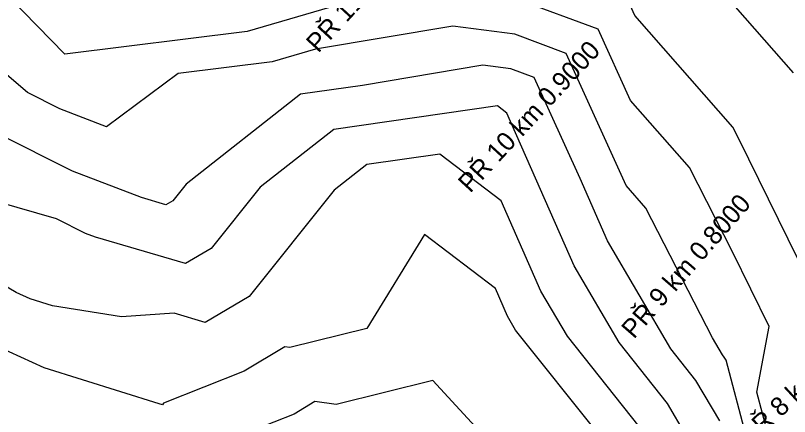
# Model space of a CAD drawing. Extents: x -549394 to -546608, y -1037055 to -1033629.
# Drawn here: x -548577.2 to -548202.8, y -1034491.4 to -1034297.2 of the extents above; entities that cross this region are included whole.
import ezdxf

# ---------------------------------------------------------------- set-up
doc = ezdxf.new("R2010")
doc.units = 0
for name, color, linetype in [('hlavni_vrst', 7, 'Continuous'), ('norm_vrst', 7, 'Continuous'), ('x_popis_pricne_rezy_C21', 7, 'Continuous')]:
    doc.layers.add(name, color=color, linetype=linetype)

msp = doc.modelspace()

# ---------------------------------------------------------------- linework, layer by layer
at = {"layer": 'hlavni_vrst'}
for p, q in [((-548351.11, -1034321.27), (-548409.39, -1034331.03)), ((-548337.6, -1034323), (-548351.11, -1034321.27)), ((-548326.39, -1034327.19), (-548337.6, -1034323)), ((-548304.14, -1034376.15), (-548326.39, -1034327.19)), ((-548409.39, -1034331.03), (-548439.33, -1034335.33)), ((-548439.33, -1034335.33), (-548494.69, -1034378.78)), ((-548549.58, -1034372.48), (-548588.64, -1034352.94)), ((-548516.22, -1034385.34), (-548549.58, -1034372.48)), ((-548494.69, -1034378.78), (-548501.11, -1034386.84)), ((-548290.88, -1034406.26), (-548304.14, -1034376.15)), ((-548504.43, -1034388.79), (-548516.22, -1034385.34)), ((-548501.11, -1034386.84), (-548504.43, -1034388.79)), ((-548260.31, -1034458.52), (-548290.88, -1034406.26)), ((-548248.12, -1034473.83), (-548260.31, -1034458.52)), ((-548236.61, -1034493.43), (-548248.12, -1034473.83))]:
    msp.add_line(p, q, dxfattribs=at)
at = {"layer": 'norm_vrst'}
for p, q in [((-548553.29, -1034315.9), (-548606.49, -1034261.26)), ((-548407.21, -1034287.96), (-548465.15, -1034304.87)), ((-548295.38, -1034303.83), (-548333.91, -1034289.41)), ((-548277.6, -1034297.17), (-548279.88, -1034292.16)), ((-548229.05, -1034292.94), (-548201.05, -1034324.93)), ((-548230.26, -1034351.27), (-548277.6, -1034297.17)), ((-548365.73, -1034302.37), (-548432.07, -1034313.48)), ((-548335.75, -1034306.21), (-548365.73, -1034302.37)), ((-548279.69, -1034338.37), (-548295.38, -1034303.83)), ((-548465.15, -1034304.87), (-548553.29, -1034315.9)), ((-548310.89, -1034315.51), (-548335.75, -1034306.21)), ((-548432.07, -1034313.48), (-548453.11, -1034319.62)), ((-548281.78, -1034379.57), (-548310.89, -1034315.51)), ((-548571.43, -1034334.47), (-548587.9, -1034320.42)), ((-548453.11, -1034319.62), (-548498.48, -1034325.29)), ((-548498.48, -1034325.29), (-548533.12, -1034351.03)), ((-548555.75, -1034342.31), (-548571.43, -1034334.47)), ((-548344.13, -1034340.96), (-548423.27, -1034352.32)), ((-548339.6, -1034344.42), (-548344.13, -1034340.96)), ((-548251.29, -1034370.83), (-548279.69, -1034338.37)), ((-548533.12, -1034351.03), (-548555.75, -1034342.31)), ((-548306.99, -1034418.43), (-548339.6, -1034344.42)), ((-548423.27, -1034352.32), (-548458.85, -1034380.25)), ((-548227.23, -1034357.2), (-548230.26, -1034351.27)), ((-548190.3, -1034432.56), (-548227.23, -1034357.2)), ((-548372.03, -1034364.26), (-548407.2, -1034369.31)), ((-548342.35, -1034386.93), (-548372.03, -1034364.26)), ((-548407.2, -1034369.31), (-548423.02, -1034381.72)), ((-548230.4, -1034411.67), (-548251.29, -1034370.83)), ((-548458.85, -1034380.25), (-548482.64, -1034410.07)), ((-548423.02, -1034381.72), (-548464.16, -1034433.3)), ((-548272.31, -1034390.39), (-548281.78, -1034379.57)), ((-548557.36, -1034395.67), (-548588.13, -1034386.75)), ((-548323.1, -1034430.61), (-548342.35, -1034386.93)), ((-548240.14, -1034453.28), (-548272.31, -1034390.39)), ((-548543.41, -1034402.65), (-548557.36, -1034395.67)), ((-548576.92, -1034431.22), (-548628.29, -1034401.66)), ((-548538.56, -1034404.52), (-548543.41, -1034402.65)), ((-548494.91, -1034417.3), (-548538.56, -1034404.52)), ((-548379.33, -1034403.29), (-548407.26, -1034448.7)), ((-548345.09, -1034429.44), (-548379.33, -1034403.29)), ((-548482.64, -1034410.07), (-548494.91, -1034417.3)), ((-548212.7, -1034447.78), (-548230.4, -1034411.67)), ((-548285.31, -1034455.5), (-548306.99, -1034418.43)), ((-548570.13, -1034434.34), (-548576.92, -1034431.22)), ((-548339.21, -1034442.78), (-548345.09, -1034429.44)), ((-548310.3, -1034452.49), (-548323.1, -1034430.61)), ((-548559.27, -1034437.72), (-548570.13, -1034434.34)), ((-548464.16, -1034433.3), (-548485.39, -1034445.81)), ((-548525.99, -1034443.12), (-548559.27, -1034437.72)), ((-548500.52, -1034441.38), (-548525.99, -1034443.12)), ((-548485.39, -1034445.81), (-548500.52, -1034441.38)), ((-548335.3, -1034449.47), (-548339.21, -1034442.78)), ((-548407.26, -1034448.7), (-548444.44, -1034457.91)), ((-548289.24, -1034507.32), (-548335.3, -1034449.47)), ((-548218.68, -1034479.5), (-548212.7, -1034447.78)), ((-548563.3, -1034467.8), (-548599.62, -1034451.14)), ((-548275.53, -1034496.16), (-548310.3, -1034452.49)), ((-548235.31, -1034461.54), (-548240.14, -1034453.28)), ((-548446.94, -1034457.6), (-548466.59, -1034469.42)), ((-548444.44, -1034457.91), (-548446.94, -1034457.6)), ((-548261.82, -1034485), (-548285.31, -1034455.5)), ((-548234.41, -1034462.67), (-548235.31, -1034461.54)), ((-548233.55, -1034464.12), (-548234.41, -1034462.67)), ((-548211.81, -1034546.33), (-548233.55, -1034464.12)), ((-548507.64, -1034485.13), (-548563.3, -1034467.8)), ((-548466.59, -1034469.42), (-548505.56, -1034484.82)), ((-548375.32, -1034473.87), (-548422.06, -1034485.46)), ((-548343.1, -1034509.02), (-548375.32, -1034473.87)), ((-548202.9, -1034539.18), (-548218.68, -1034479.5)), ((-548506.07, -1034485.64), (-548507.64, -1034485.13)), ((-548505.56, -1034484.82), (-548506.07, -1034485.64)), ((-548432.37, -1034484.14), (-548442.35, -1034490.14)), ((-548422.06, -1034485.46), (-548432.37, -1034484.14)), ((-548239.67, -1034522.74), (-548261.82, -1034485)), ((-548442.35, -1034490.14), (-548462.11, -1034497.96))]:
    msp.add_line(p, q, dxfattribs=at)

# ---------------------------------------------------------------- texts
at = {"layer": 'x_popis_pricne_rezy_C21'}
for s, rotation, p in [('PŘ 11 km 1.0000', 47.3078, (-548430.79, -1034315.67)), ('PŘ 10 km 0.9000', 47.3078, (-548357.29, -1034383.48)), ('PŘ 9 km 0.8000', 48.9228, (-548278.09, -1034454.16)), ('PŘ 8 km 0.7000', 42.6945, (-548221.92, -1034505.62))]:
    msp.add_text(s, height=9.0627, rotation=rotation, dxfattribs=at).set_placement(p)

doc.saveas('drawing.dxf')
